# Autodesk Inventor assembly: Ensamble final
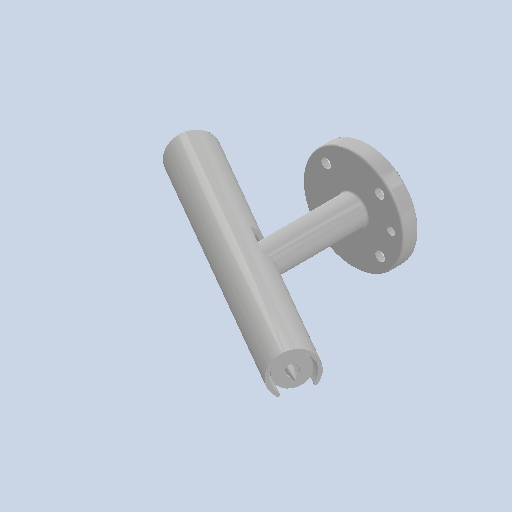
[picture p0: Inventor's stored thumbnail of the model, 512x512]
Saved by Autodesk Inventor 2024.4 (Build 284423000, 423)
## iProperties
Created: 2025-06
Part Number: Ensamble final
Document SubType Name: Assembly
Designer: AdminForWorker
Title: Ensamble final v3
Author: AdminForWorker
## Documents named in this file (6)
- c:\worker\convert-fusion-r02-cosv3\tmp\job-1\258\temp\files\b1f5cff6-2824-4cab-9e49-e311ea18fd89\dc3dc280-55b4-4c78-8b84-b06a2d9313ce.iam
- c:\worker\convert-fusion-r02-cosv3\tmp\job-1\258\temp\files\b1f5cff6-2824-4cab-9e49-e311ea18fd89\base1 v12.ipt
- c:\worker\convert-fusion-r02-cosv3\tmp\job-1\258\temp\files\b1f5cff6-2824-4cab-9e49-e311ea18fd89\marcador v2.ipt
- c:\worker\convert-fusion-r02-cosv3\tmp\job-1\258\temp\files\b1f5cff6-2824-4cab-9e49-e311ea18fd89\94125K631_Compression Springs.ipt
- c:\worker\convert-fusion-r02-cosv3\tmp\job-1\258\temp\files\b1f5cff6-2824-4cab-9e49-e311ea18fd89\basemarcador2 v15.ipt
- c:\worker\convert-fusion-r02-cosv3\tmp\job-1\258\temp\files\b1f5cff6-2824-4cab-9e49-e311ea18fd89\resorte v2.iam
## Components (5 placed, 5 different names)
1. base1 v12:1
2. marcador v2:1
3. 94125K631_Compression Springs:1
4. basemarcador2 v15:1
5. resorte v2:1 [sub-assembly]
